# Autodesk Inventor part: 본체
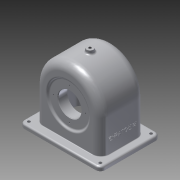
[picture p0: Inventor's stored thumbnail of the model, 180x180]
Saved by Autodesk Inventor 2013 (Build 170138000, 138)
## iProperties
Created: 2016-01
Part Number: 본체
Material: 알루미늄 6061
Document SubType Name: Modeling
Designer: cad10
Density: 2.40731 g/cm^3
Mass: 807.483 g
Surface Area: 1019.49 cm^2
Volume: 335.429 cm^3
Author: cad10
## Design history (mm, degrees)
sketch "스케치1"
  geometry: L1 (57, 0)-(57, -64); L2 (57, -64)-(-57, -64); L3 (-57, -64)-(-57, 0); L4 (0, 12.214)-(0, 34.551); A1 r 57 centre (0, 0) between (57, 0) and (-57, 0); 1 further point
  constraints: 8 end point, 2 parallel, 2 point on circle, 1 centre point, 1 coincident, 1 other
  dimensions: "d1" = 57 radius of A1; "d3" = 114 distance of L3.end L1.start; "d4" = 64 distance of L1.start L1.end
extrude "돌출1" new body sketch "스케치1" distance "d5" = 77; taper "d6" = 0 deg
node "작업 평면1"
sketch "스케치2"
  geometry: L1 (57, 0)-(-57, 0) reference; L2 (-57, 0)-(-57, 77) reference; L3 (57, 0)-(57, 77) reference; L4 (57, 77)-(-57, 77) reference; L5 (0, 0)-(0, 77); L6 (-57, 38.5)-(57, 38.5); L7 (-62, 90.5)-(62, 90.5); L8 (70, 82.5)-(70, -5.5); L9 (62, -13.5)-(-62, -13.5); L10 (-70, -5.5)-(-70, 82.5); A1 r 8 centre (-62, 82.5) between (-62, 90.5) and (-70, 82.5); A2 r 8 centre (62, 82.5) between (70, 82.5) and (62, 90.5); A3 r 8 centre (62, -5.5) between (62, -13.5) and (70, -5.5); A4 r 8 centre (-62, -5.5) between (-70, -5.5) and (-62, -13.5); 3 further points
  constraints: 12 end point, 8 point on circle, 8 tangent, 6 point on line, 4 centre point, 3 equal radius, 3 midpoint, 2 parallel, 1 horizontal, 1 perpendicular, 2 other
  dimensions: "d10" = 104 distance of point (70, 90.5) point (70, -13.5); "d11" = 140 distance of point (70, -13.5) point (-70, -13.5); "d13" = 8 radius of A1
extrude "돌출2" join sketch "스케치2" distance "d14" = 7; taper "d15" = 0 deg
sketch "스케치3"
  geometry: C1 r 2.5 at (-62, -5.5); C2 r 2.5 at (-62, 82.5); C3 r 2.5 at (62, 82.5); C4 r 2.5 at (62, -5.5); A1 r 8 centre (-62, 82.5) between (-62, 90.5) and (-70, 82.5) reference; A2 r 8 centre (-62, -5.5) between (-70, -5.5) and (-62, -13.5) reference; A3 r 8 centre (62, -5.5) between (62, -13.5) and (70, -5.5) reference; A4 r 8 centre (62, 82.5) between (70, 82.5) and (62, 90.5) reference; 1 further point
  constraints: 4 centre point, 4 coincident
  dimensions: "d16" = 5 diameter of C1; "d18" = 5 diameter of C2; "d19" = 5 diameter of C3; "d20" = 5 diameter of C4
extrude "돌출3" cut sketch "스케치3" distance "d21" = 7; taper "d22" = 0 deg
node "작업축1"
node "작업 평면2"
sketch "스케치5"
  geometry: L1 (-51, 0)-(-51, -76.657); L2 (51, 0)-(51, -76.657); L3 (51, -76.657)-(-51, -76.657); A1 r 51 centre (0, 0) between (51, 0) and (-51, 0); 1 further point
  constraints: 6 end point, 3 point on circle, 1 centre point, 1 coincident, 1 perpendicular, 1 point on line, 1 tangent, 1 vertical
  dimensions: "d33" = 102 diameter of A1; "d110" = 102 distance of L2.end L1.end
extrude "돌출4" cut sketch "스케치5" distance "d35" = 67; taper "d36" = 0 deg
sketch "스케치6"
  geometry: L1 (-16.832, -4)-(105.044, -4); L2 (72, -64)-(5, -64) reference; L3 (19, -4)-(19, 24); L4 (19, 24)-(2.235, 38.067); L5 (2.235, 38.067)-(2.235, -4); L6 (19, -4)-(2.235, -4); L7 (0, 0)-(0, 57) reference; 1 further point
  constraints: 10 end point, 2 perpendicular, 2 point on line, 1 coincident, 1 collinear, 1 horizontal
  dimensions: "d37" = 60 distance between parallel lines of L1 L2; "d39" = 50 deg angle of L4 L3; "d40" = 56 diameter of point (19, 24) L1; "d109" = 19 distance between parallel lines of L3 L7
revolve "회전1" sketch "스케치6" stored, may be unused: angle "d41" = 90 deg
node "작업 평면3"
sketch "스케치7"
  geometry: L1 (-57, 0)-(-57, 77) reference; L2 (57, 0)-(57, 77) reference; L3 (-57, 38.5)-(57, 38.5); C1 r 6 at (0, 38.5); 1 further point
  constraints: 2 end point, 2 midpoint, 1 centre point, 1 vertical alignment
  dimensions: "d43" = 12 diameter of C1; "d45" = 38.5 distance of C1.centre point (0, 0)
extrude "돌출5" join sketch "스케치7" stored distance "d46" = 67; taper "d47" = 0 deg
sketch "스케치8"
  geometry: L1 (-62, 64)-(62, 64) reference; C1 r 31 at (0, 4); A1 r 57 centre (0, 0) between (-57, 0) and (57, 0) reference
  constraints: 1 centre point, 1 vertical alignment
  dimensions: "d48" = 62 diameter of C1; "d50" = 60 distance from line of C1.centre L1
extrude "돌출6" join sketch "스케치8" distance "d51" = 10; taper "d52" = 0 deg
node "작업축2"
sketch "스케치9"
  geometry: L1 (0, 33.416)-(3, 30.899); L2 (3, 30.899)-(3, -20.71); L3 (0, 0)-(0, 57) reference; L4 (5, 35.747)-(19, 24) reference; L5 (-34.3, -4)-(111.3, -4) reference; L6 (3, -4)-(0, -4); L7 (0, -4)-(0, 33.416); L8 (0, 57)-(0, 43)
  constraints: 10 end point, 5 point on line, 1 vertical
  dimensions: "d53" = 3 distance between parallel lines of L3 L2; "d54" = 50 deg angle of L1 L2; "d55" = 5 distance from line of L1 L4.start; "d107" = 14 distance of L3.end L8.end
revolve "회전2" sketch "스케치9" stored, may be unused: angle "d56" = 90 deg
sketch "스케치10"
  geometry: L1 (-34.32, -4)-(111.418, -4) reference; L2 (-6.987, 16)-(90.598, 16); L3 (-6.987, 16)-(-6.987, -4); L4 (90.598, 16)-(90.598, -4); L5 (90.598, -4)-(-6.987, -4); 1 further point
  constraints: 8 end point, 3 perpendicular, 2 point on line, 1 parallel
  dimensions: "d57" = 40 diameter of L2 L1
revolve "회전3" sketch "스케치10" stored, may be unused: angle "d58" = 90 deg
sketch "스케치11" dims "d59" = 56
  geometry: C1 r 34.899 at (0, 0) reference; 3 further points
  constraints: 1 coincident, 3 other
hole "구멍1" sketch "스케치11" at (28, 0) diameter "d61" = 2.459; stored, may be unused: countersink angle "d65" = 90 deg, drill point angle "d67" = 118 deg; dims "d62" = 7, "d63" = 4, "d64" = 2, "d66" = 9
sketch "스케치12" dims "d71" = 48
  geometry: C1 r 31 at (0, 0) reference; 3 further points
  constraints: 1 coincident, 1 vertical alignment, 2 other
hole "구멍2" sketch "스케치12" at (0, -24) diameter "d73" = 2.459; stored, may be unused: countersink angle "d77" = 90 deg, drill point angle "d79" = 118 deg; dims "d74" = 6, "d75" = 4, "d76" = 2, "d78" = 8
sketch "스케치13"
  geometry: C1 r 6 at (0, 0) reference; 2 further points
  constraints: 1 coincident
hole "구멍3" sketch "스케치13" at (0, 0) diameter "d83" = 4.459; stored, may be unused: countersink angle "d87" = 90 deg, drill point angle "d89" = 118 deg; dims "d84" = 25, "d85" = 4, "d86" = 2, "d88" = 26
fillet "모깎기1" dims "d90" = 9
fillet "모깎기2" dims "d91" = 9
fillet "모깎기3" dims "d92" = 14
fillet "모깎기4" dims "d93" = 1
fillet "모깎기5" dims "d94" = 3
chamfer "모따기1" distance "d95" = 1; stored, may be unused: second distance "d96" = 2, angle "d97" = 45 deg
chamfer "모따기2" distance "d98" = 1; stored, may be unused: second distance "d99" = 2, angle "d100" = 45 deg
node "작업 평면4"
sketch "스케치14"
  geometry: L1 (0, -14)-(56, -14) reference; L2 (64, 68.5)-(64, -19.5) reference; 2 further points
  constraints: 1 other
  dimensions: "d102" = 38 distance from line of L1 point (34, 24); "d103" = 30 distance from line of point (34, 24) L2
feature "엠보싱1" sketch "스케치14" dims "d10" = 104, "d11" = 140, "d13" = 8, "d104" = 0.5, "d105" = 0
fillet "모깎기6" dims "d106" = 3
node "솔리드1"
pattern_circular "원형 패턴1" dims angle "d69" = 360 deg
pattern_circular "원형 패턴2" dims angle "d81" = 360 deg
other parameters: "d7" = -64, "d32" = -5, "d42" = 63, "d101" = 22.25
